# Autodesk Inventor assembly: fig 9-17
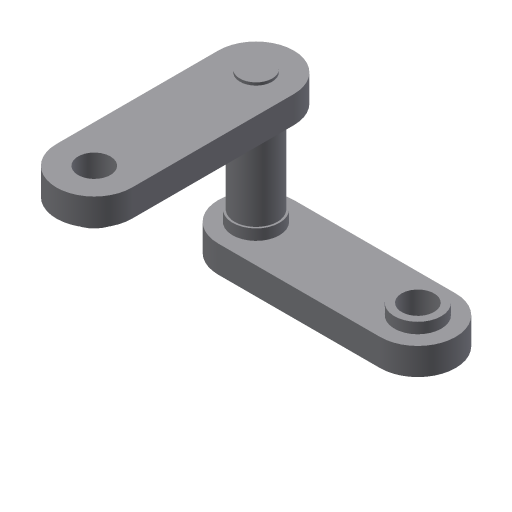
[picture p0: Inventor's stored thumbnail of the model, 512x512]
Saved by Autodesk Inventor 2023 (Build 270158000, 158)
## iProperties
Created: 2002-01
Part Number: fig 9-17
Document SubType Name: Assembly
Designer: ***
Control State: 0
Master: False
Checked Out: False
Shininess: 64.0
Length Units: 11269
Angle Units: 11279
Time Units: 11290
Mass Units: 11283
Length Display Precision: 3
Angle Display Precision: 2
Density: 0.0
Volumn: 0.0
Area: 0.0
PropertySet Name: Model Information
Author: ***
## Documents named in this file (3)
- D:\PROJECTS\Project 2022\Autodesk Inventor For Professional 2023\RESOURCES INVENTOR 2023\RESOURCES INVENTOR 2023\Inventor_2023_Part\Inventor_2023_Part\c09_Inv_2023_prt\fig 9-17.iam
- D:\PROJECTS\Project 2022\Autodesk Inventor For Professional 2023\RESOURCES INVENTOR 2023\RESOURCES INVENTOR 2023\Inventor_2023_Part\Inventor_2023_Part\c09_Inv_2023_prt\Part5.ipt
- D:\PROJECTS\Project 2022\Autodesk Inventor For Professional 2023\RESOURCES INVENTOR 2023\RESOURCES INVENTOR 2023\Inventor_2023_Part\Inventor_2023_Part\c09_Inv_2023_prt\Part6.ipt
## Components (3 placed, 2 different names)
1. Part5:1 — Insert:1
2. Part6:1 — Insert:1, Insert:2
3. Part5:2 — Insert:2
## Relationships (2: Insert 2)
- Insert:1: Part5:1 ↔ Part6:1
- Insert:2: Part6:1 ↔ Part5:2
